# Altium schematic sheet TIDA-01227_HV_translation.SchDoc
size 431 x 279 mm; Date: Not shown in title block; ApprovedBy: Not shown in title block; CheckedBy: Not shown in title block; Author: Not shown in title block; CompanyName: Not shown in title block; Engineer: Not shown in title block; Organization: Not shown in title block; Address1: Not shown in title block; Address2: Not shown in title block; Address3: Not shown in title block; Address4: Not shown in title block; DocumentNumber: 3; Revision: Use project parameter SCH_Rev; SheetNumber: 3; SheetTotal: 4; PageSetup: Record=PageOptions¦CenterHorizontal=True¦CenterVertical=True¦PrintScale=1.00¦XCorrection=1.00¦YCorrection=1.00¦PrintKind=0¦BorderSize=5000000¦LeftOffset=0¦BottomOffset=0¦Orientation=2¦PaperLength=1000¦PaperWidth=1000¦Scale=100¦PaperSource=15¦PrintQuality=600¦MediaType=1¦DitherType=10¦PaperKind=Letter¦PrintScaleMode=1
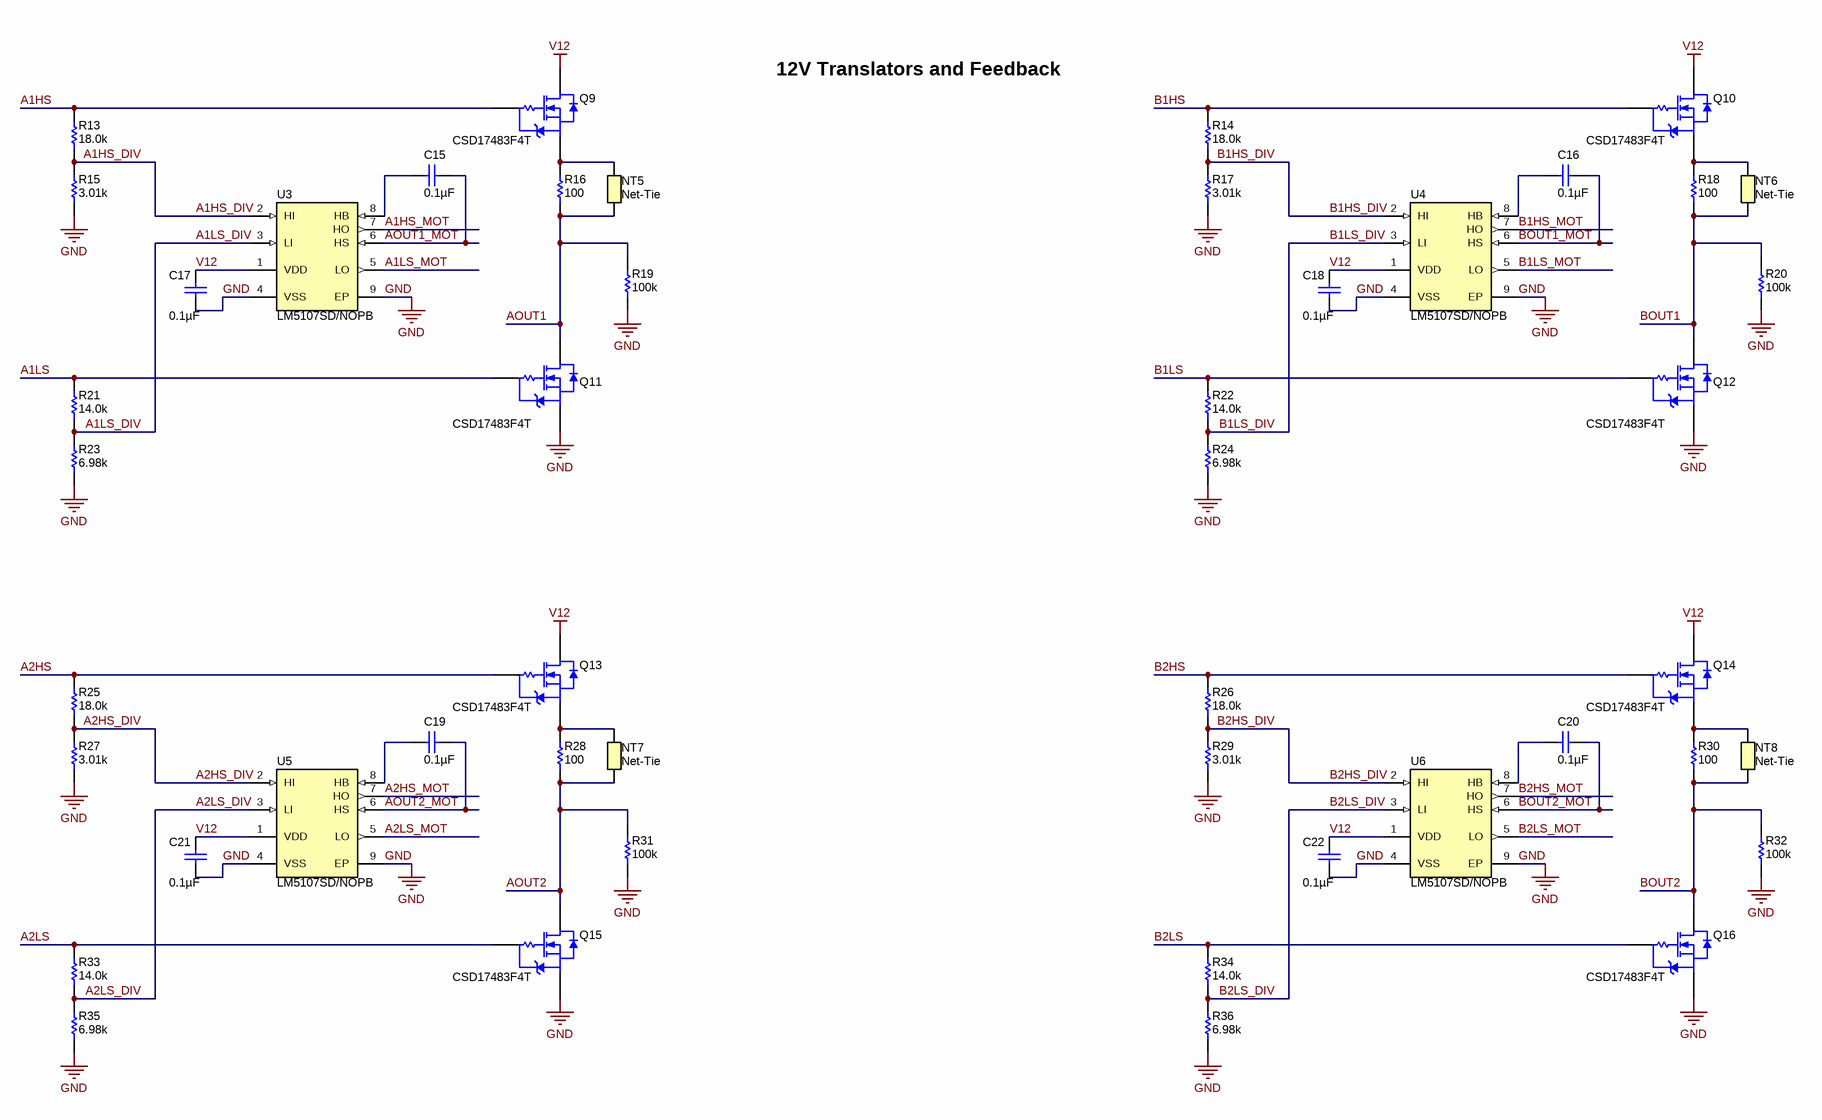
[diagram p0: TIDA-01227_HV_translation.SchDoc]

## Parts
C15  ValueDisplayed: 0.1µF  [0402L]  (hidden comment: C1005X7R1E104M050BB)
C16  ValueDisplayed: 0.1µF  [0402L]  (hidden comment: C1005X7R1E104M050BB)
C17  ValueDisplayed: 0.1µF  [0402L]  (hidden comment: C1005X7R1E104M050BB)
C18  ValueDisplayed: 0.1µF  [0402L]  (hidden comment: C1005X7R1E104M050BB)
C19  ValueDisplayed: 0.1µF  [0402L]  (hidden comment: C1005X7R1E104M050BB)
C20  ValueDisplayed: 0.1µF  [0402L]  (hidden comment: C1005X7R1E104M050BB)
C21  ValueDisplayed: 0.1µF  [0402L]  (hidden comment: C1005X7R1E104M050BB)
C22  ValueDisplayed: 0.1µF  [0402L]  (hidden comment: C1005X7R1E104M050BB)
NT5  Net-Tie  [Net-Tie_10mil]  (net tie, no BOM)
NT6  Net-Tie  [Net-Tie_10mil]  (net tie, no BOM)
NT7  Net-Tie  [Net-Tie_10mil]  (net tie, no BOM)
NT8  Net-Tie  [Net-Tie_10mil]  (net tie, no BOM)
Q9  CSD17483F4T  [YJC0003A]
Q10  CSD17483F4T  [YJC0003A]
Q11  CSD17483F4T  [YJC0003A]
Q12  CSD17483F4T  [YJC0003A]
Q13  CSD17483F4T  [YJC0003A]
Q14  CSD17483F4T  [YJC0003A]
Q15  CSD17483F4T  [YJC0003A]
Q16  CSD17483F4T  [YJC0003A]
R13  ValueDisplayed: 18.0k  [0402L]  (hidden comment: CRCW040218K0FKED)
R14  ValueDisplayed: 18.0k  [0402L]  (hidden comment: CRCW040218K0FKED)
R15  ValueDisplayed: 3.01k  [0402L]  (hidden comment: CRCW04023K01FKED)
R16  ValueDisplayed: 100  [0603L]  (hidden comment: CRCW0603100RJNEA)
R17  ValueDisplayed: 3.01k  [0402L]  (hidden comment: CRCW04023K01FKED)
R18  ValueDisplayed: 100  [0603L]  (hidden comment: CRCW0603100RJNEA)
R19  ValueDisplayed: 100k  [0402L]  (hidden comment: CRCW0402100KFKED)
R20  ValueDisplayed: 100k  [0402L]  (hidden comment: CRCW0402100KFKED)
R21  ValueDisplayed: 14.0k  [0402L]  (hidden comment: CRCW040214K0FKED)
R22  ValueDisplayed: 14.0k  [0402L]  (hidden comment: CRCW040214K0FKED)
R23  ValueDisplayed: 6.98k  [0402L]  (hidden comment: CRCW04026K98FKED)
R24  ValueDisplayed: 6.98k  [0402L]  (hidden comment: CRCW04026K98FKED)
R25  ValueDisplayed: 18.0k  [0402L]  (hidden comment: CRCW040218K0FKED)
R26  ValueDisplayed: 18.0k  [0402L]  (hidden comment: CRCW040218K0FKED)
R27  ValueDisplayed: 3.01k  [0402L]  (hidden comment: CRCW04023K01FKED)
R28  ValueDisplayed: 100  [0603L]  (hidden comment: CRCW0603100RJNEA)
R29  ValueDisplayed: 3.01k  [0402L]  (hidden comment: CRCW04023K01FKED)
R30  ValueDisplayed: 100  [0603L]  (hidden comment: CRCW0603100RJNEA)
R31  ValueDisplayed: 100k  [0402L]  (hidden comment: CRCW0402100KFKED)
R32  ValueDisplayed: 100k  [0402L]  (hidden comment: CRCW0402100KFKED)
R33  ValueDisplayed: 14.0k  [0402L]  (hidden comment: CRCW040214K0FKED)
R34  ValueDisplayed: 14.0k  [0402L]  (hidden comment: CRCW040214K0FKED)
R35  ValueDisplayed: 6.98k  [0402L]  (hidden comment: CRCW04026K98FKED)
R36  ValueDisplayed: 6.98k  [0402L]  (hidden comment: CRCW04026K98FKED)
U3  LM5107SD/NOPB  [SDC08A]
U4  LM5107SD/NOPB  [SDC08A]
U5  LM5107SD/NOPB  [SDC08A]
U6  LM5107SD/NOPB  [SDC08A]

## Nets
GND: C17.2 C18.2 C21.2 C22.2 Q11.2(S) Q12.2(S) Q15.2(S) Q16.2(S) R15.1 R17.1 R19.1 R20.1 R23.1 R24.1 R27.1 R29.1 R31.1 R32.1 R35.1 R36.1 U3.4(VSS) U3.9(EP) U4.4(VSS) U4.9(EP) U5.4(VSS) U5.9(EP) U6.4(VSS) U6.9(EP)
V12: C17.1 C18.1 C21.1 C22.1 Q9.3(D) Q10.3(D) Q13.3(D) Q14.3(D) U3.1(VDD) U4.1(VDD) U5.1(VDD) U6.1(VDD)
A1HS: Q9.1(G) R13.2
A1HS_DIV: R13.1 R15.2 U3.2(HI)
A1HS_MOT: U3.7(HO)
A1LS: Q11.1(G) R21.2
A1LS_DIV: R21.1 R23.2 U3.3(LI)
A1LS_MOT: U3.5(LO)
A2HS: Q13.1(G) R25.2
A2HS_DIV: R25.1 R27.2 U5.2(HI)
A2HS_MOT: U5.7(HO)
A2LS: Q15.1(G) R33.2
A2LS_DIV: R33.1 R35.2 U5.3(LI)
A2LS_MOT: U5.5(LO)
AOUT1: NT5.1 Q11.3(D) R16.1 R19.2
AOUT1_MOT: C15.1 U3.6(HS)
AOUT2: NT7.1 Q15.3(D) R28.1 R31.2
AOUT2_MOT: C19.1 U5.6(HS)
B1HS: Q10.1(G) R14.2
B1HS_DIV: R14.1 R17.2 U4.2(HI)
B1HS_MOT: U4.7(HO)
B1LS: Q12.1(G) R22.2
B1LS_DIV: R22.1 R24.2 U4.3(LI)
B1LS_MOT: U4.5(LO)
B2HS: Q14.1(G) R26.2
B2HS_DIV: R26.1 R29.2 U6.2(HI)
B2HS_MOT: U6.7(HO)
B2LS: Q16.1(G) R34.2
B2LS_DIV: R34.1 R36.2 U6.3(LI)
B2LS_MOT: U6.5(LO)
BOUT1: NT6.1 Q12.3(D) R18.1 R20.2
BOUT1_MOT: C16.1 U4.6(HS)
BOUT2: NT8.1 Q16.3(D) R30.1 R32.2
BOUT2_MOT: C20.1 U6.6(HS)
NetC15_2: C15.2 U3.8(HB)
NetC16_2: C16.2 U4.8(HB)
NetC19_2: C19.2 U5.8(HB)
NetC20_2: C20.2 U6.8(HB)
NetNT5_2: NT5.2 Q9.2(S) R16.2
NetNT6_2: NT6.2 Q10.2(S) R18.2
NetNT7_2: NT7.2 Q13.2(S) R28.2
NetNT8_2: NT8.2 Q14.2(S) R30.2

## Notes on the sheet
- 12V Translators and Feedback

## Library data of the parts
C15-C22 = C1005X7R1E104M050BB: CAP, CERM, 0.1 µF, 25 V, +/- 20%, X7R, 0402; Manufacturer: TDK; Polarized: N; CompType: Capacitor; Value: 0.1uF; U/M: EA; Cap_F: 0.0000001; Tolerance_%: 20; Value1: Unknown; VDC_V: 25; Value2: 25V; TaMin_C: -55; TaMax_C: 125; Cap_Case: 0402; SizeArea_mm2: 0.5; SizeAreaWB_mm2: 3; SizeX_mm: 1; SizeZ_mm: 0.6; AEC Category: Q200
NT5-NT8 = Net-Tie: Single point connection between nets.; SymbolCreator: codlsc
Q9-Q16 = CSD17483F4T: MOSFET, N/P-CH, 30 V, 1.5 A, 1.0x0.35x0.6mm; Manufacturer: Texas Instruments; Alternate Manufacturer: None; SymbolCreator: a0411947; U/M: EA; ChType: N; Value: 30V; VdsMax_V: 30; Value1: 0.2 ohm; Rdson45_ohm: 0.2; Value2: 1.01 nC; QgTyp_nC: 1.01; Vgs_V: 12; IdsMax_A: 1.5
R13 R14 R25 R26 = CRCW040218K0FKED: RES, 18.0 k, 1%, 0.063 W, AEC-Q200 Grade 0, 0402; Manufacturer: Vishay-Dale; CompType: Resistor; Value: 18.0k; Res_ohm: 18000; Value_Code: 18k0; Tolerance_%: 1; Power_W: 0.063; Value2: 0.063W; VDC_V: 50; TempCo: 100 ppm/C; SizeArea_mm2: 0.5; SizeZ_mm: 0.6; U/M: EA; AEC Category: Q200; AEC Qualified: Y; AEC Grade: 0
R15 R17 R27 R29 = CRCW04023K01FKED: RES, 3.01 k, 1%, 0.063 W, 0402; Manufacturer: Vishay-Dale; CompType: Resistor; Value: 3.01k; Res_ohm: 3010; Value_Code: 3k01; Tolerance_%: 1; Power_W: 0.063; Value2: 0.063W; VDC_V: 50; TempCo: 100 ppm/C; SizeArea_mm2: 0.5; SizeZ_mm: 0.6; EIA_Code: E96; U/M: EA; AEC Category: Q200
R16 R18 R28 R30 = CRCW0603100RJNEA: RES, 100, 5%, 0.1 W, 0603; Manufacturer: Vishay-Dale; CompType: Resistor; Value: 100; Value_Code: 100R; Tolerance_%: 5; Power_W: 0.1; Value2: 0.1W; VDC_V: 75; TempCo: 200 ppm/C; EIA_Code: E24; U/M: EA; SizeArea_mm2: 1.28; SizeX_mm: 1.6; SizeY_mm: 0.8; SizeZ_mm: 1; AEC Category: Q200
R19 R20 R31 R32 = CRCW0402100KFKED: RES, 100 k, 1%, 0.063 W, 0402; Manufacturer: Vishay-Dale; CompType: Resistor; Value: 100k; Res_ohm: 100000; Tolerance_%: 1; Power_W: 0.063; Value2: 0.063W; VDC_V: 50; TempCo: 100 ppm/C; EIA_Code: E96; U/M: EA
R21 R22 R33 R34 = CRCW040214K0FKED: RES, 14.0 k, 1%, 0.063 W, 0402; Manufacturer: Vishay-Dale; CompType: Resistor; Value: 14.0k; Res_ohm: 14000; Value_Code: 14k0; Tolerance_%: 1; Power_W: 0.063; Value2: 0.063W; VDC_V: 50; TempCo: 100 ppm/C; SizeArea_mm2: 0.5; SizeZ_mm: 0.6; EIA_Code: E96; U/M: EA; AEC Category: Q200
R23 R24 R35 R36 = CRCW04026K98FKED: RES, 6.98 k, 1%, 0.063 W, 0402; Manufacturer: Vishay-Dale; CompType: Resistor; Value: 6.98k; Res_ohm: 6980; Value_Code: 6k98; Tolerance_%: 1; Power_W: 0.063; Value2: 0.063W; VDC_V: 50; TempCo: 100 ppm/C; SizeArea_mm2: 0.5; SizeZ_mm: 0.6; EIA_Code: E96; U/M: EA; AEC Category: Q200
U3-U6 = LM5107SD/NOPB: 100V / 1.4A Peak Half-Bridge Gate Driver, 8-pin LLP, Pb-Free; Manufacturer: Texas Instruments; PackageTopMarking: NS*UZXYTT*L5107SD; PowerWise: N; CompType: MiscPower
